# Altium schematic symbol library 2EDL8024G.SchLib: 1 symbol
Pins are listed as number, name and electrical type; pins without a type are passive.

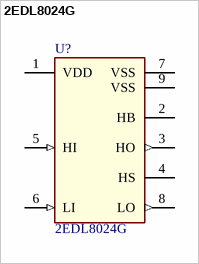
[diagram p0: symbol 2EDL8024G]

## 2EDL8024G
designator U?
EiceDRIVER; Manufacturer: InfineonTechnologies; ManufacturerPartNumber: 2EDL8113G
pins: 1 VDD (power) "Gate drive supply", 2 HB "High-side gate driver bootstrap rail", 3 HO (out) "High-side gate driver output", 4 HS "High-side FET source connection", 5 HI (in) "High-side driver control input", 6 LI (in) "Low-side driver control input", 7 VSS (power) "Ground return, internally connected to exposed pad", 8 LO (out) "low-side gate driver output", 9 VSS (power) "Exposed Pad"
